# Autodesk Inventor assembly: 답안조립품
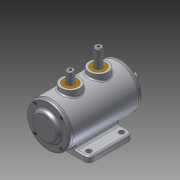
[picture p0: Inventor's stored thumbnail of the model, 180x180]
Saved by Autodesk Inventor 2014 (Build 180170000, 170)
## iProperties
Created: 2014-12
Part Number: 답안조립품
Document SubType Name: Assembly
Designer: Owner
Author: Owner
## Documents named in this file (10)
- C:\Users\Owner\Desktop\441223V1005\답안조립품.iam
- C:\Users\Owner\Desktop\441223V1005\본체.ipt
- C:\Users\Owner\Desktop\441223V1005\M4-소켓머리.ipt
- C:\Users\Owner\Desktop\441223V1005\뒷커버.ipt
- C:\Users\Owner\Desktop\441223V1005\베어링 6203.ipt
- C:\Users\Owner\Desktop\441223V1005\부시.ipt
- C:\Users\Owner\Desktop\441223V1005\슬라이더.ipt
- C:\Users\Owner\Desktop\441223V1005\앞커버.ipt
- C:\Users\Owner\Desktop\441223V1005\오일실.ipt
- C:\Users\Owner\Desktop\441223V1005\축.ipt
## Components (11 placed, 3 different names)
1. 7-베어링 6203:1
2. 8-오일실:1
3. 7-베어링 6203:2
4. 9-M4-소켓머리:2
5. 9-M4-소켓머리:3
6. 9-M4-소켓머리:4
7. 9-M4-소켓머리:5
8. 9-M4-소켓머리:1
9. 9-M4-소켓머리:6
10. 9-M4-소켓머리:7
11. 9-M4-소켓머리:8
